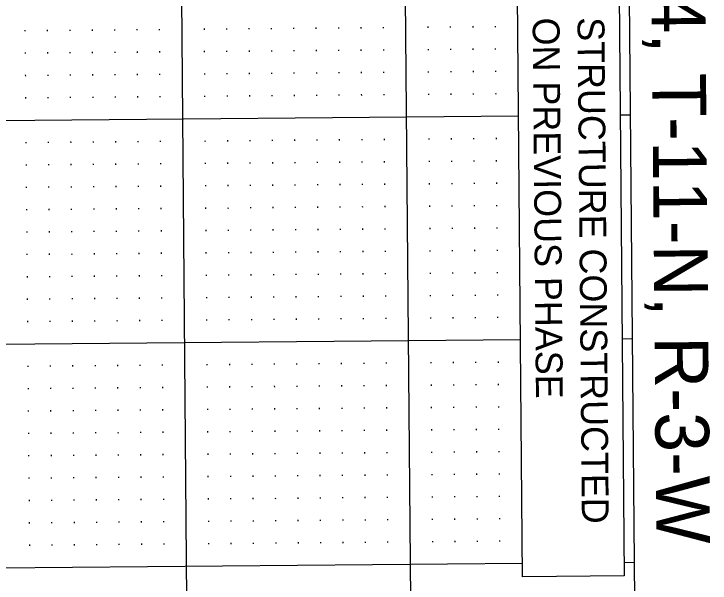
# Model space of a CAD drawing. Extents: x 2149873 to 2152007, y 140538 to 142349.
# Drawn here: x 2150345.4 to 2150500.9, y 141221.9 to 141349.1 of the extents above; entities that cross this region are included whole.
import ezdxf

# ---------------------------------------------------------------- set-up
doc = ezdxf.new("R2010")
doc.units = 0
for name, color, linetype in [('PLSS_Text', 7, 'Continuous'), ('PR_Grading_Txt', 7, 'Continuous'), ('PR_Misc_Improvement', 7, 'Continuous'), ('SHT_Profile_Grid_Major', 7, 'Continuous'), ('SHT_Profile_Grid_Minor', 7, 'Continuous'), ('SHT_Sheet_Border', 7, 'Continuous')]:
    doc.layers.add(name, color=color, linetype=linetype)

msp = doc.modelspace()

# ---------------------------------------------------------------- linework, layer by layer
at = {"layer": 'PR_Misc_Improvement'}
msp.add_lwpolyline([(2150480.33, 141379.55), (2150481.69, 141223.49), (2150459.02, 141223.29), (2150457.66, 141379.35)], close=True, dxfattribs=at)
at = {"layer": 'SHT_Profile_Grid_Major'}
for p, q in [((2150375.71, 142163.13), (2150389.5, 140588.19)), ((2150425.71, 142163.57), (2150439.49, 140588.63)), ((2149983.06, 141322.16), (2150458.12, 141326.32)), ((2149983.06, 141322.16), (2150458.12, 141326.32)), ((2150480.79, 141326.52), (2150483.04, 141326.54)), ((2150480.79, 141326.52), (2150483.04, 141326.54)), ((2149983.49, 141272.17), (2150458.56, 141276.32)), ((2150481.23, 141276.52), (2150483.48, 141276.54)), ((2149983.93, 141222.17), (2150458.99, 141226.33)), ((2150481.67, 141226.52), (2150483.91, 141226.54))]:
    msp.add_line(p, q, dxfattribs=at)
at = {"layer": 'SHT_Profile_Grid_Minor'}
for p, q in [((2150347.87, 141345.48), (2150347.87, 141345.23)), ((2150352.87, 141345.53), (2150352.87, 141345.28)), ((2150357.87, 141345.57), (2150357.87, 141345.32)), ((2150362.87, 141345.61), (2150362.87, 141345.36)), ((2150367.87, 141345.66), (2150367.87, 141345.41)), ((2150372.87, 141345.7), (2150372.87, 141345.45)), ((2150377.87, 141345.74), (2150377.87, 141345.49)), ((2150387.86, 141345.83), (2150387.87, 141345.58)), ((2150392.86, 141345.88), (2150392.87, 141345.63)), ((2150397.86, 141345.92), (2150397.87, 141345.67)), ((2150402.86, 141345.96), (2150402.87, 141345.71)), ((2150407.86, 141346.01), (2150407.87, 141345.76)), ((2150412.86, 141346.05), (2150412.87, 141345.8)), ((2150417.86, 141346.09), (2150417.87, 141345.85)), ((2150422.86, 141346.14), (2150422.87, 141345.89)), ((2150427.86, 141346.18), (2150427.87, 141345.93)), ((2150437.86, 141346.27), (2150437.87, 141346.02)), ((2150442.86, 141346.31), (2150442.86, 141346.06)), ((2150447.86, 141346.36), (2150447.86, 141346.11)), ((2150452.86, 141346.4), (2150452.86, 141346.15)), ((2150372.91, 141340.7), (2150372.91, 141340.45)), ((2150377.91, 141340.75), (2150377.91, 141340.5)), ((2150387.91, 141340.83), (2150387.91, 141340.58)), ((2150392.91, 141340.88), (2150392.91, 141340.63)), ((2150397.91, 141340.92), (2150397.91, 141340.67)), ((2150402.91, 141340.96), (2150402.91, 141340.71)), ((2150407.91, 141341.01), (2150407.91, 141340.76)), ((2150412.91, 141341.05), (2150412.91, 141340.8)), ((2150417.91, 141341.1), (2150417.91, 141340.85)), ((2150422.91, 141341.14), (2150422.91, 141340.89)), ((2150427.91, 141341.18), (2150427.91, 141340.93)), ((2150437.91, 141341.27), (2150437.91, 141341.02)), ((2150442.91, 141341.31), (2150442.91, 141341.06)), ((2150447.91, 141341.36), (2150447.91, 141341.11)), ((2150452.91, 141341.4), (2150452.91, 141341.15)), ((2150347.91, 141340.48), (2150347.91, 141340.23)), ((2150352.91, 141340.53), (2150352.91, 141340.28)), ((2150357.91, 141340.57), (2150357.91, 141340.32)), ((2150362.91, 141340.61), (2150362.91, 141340.36)), ((2150367.91, 141340.66), (2150367.91, 141340.41)), ((2150412.95, 141336.05), (2150412.95, 141335.8)), ((2150417.95, 141336.1), (2150417.95, 141335.85)), ((2150422.95, 141336.14), (2150422.95, 141335.89)), ((2150427.95, 141336.18), (2150427.95, 141335.93)), ((2150437.95, 141336.27), (2150437.95, 141336.02)), ((2150442.95, 141336.31), (2150442.95, 141336.06)), ((2150447.95, 141336.36), (2150447.95, 141336.11)), ((2150452.95, 141336.4), (2150452.95, 141336.15)), ((2150347.95, 141335.48), (2150347.96, 141335.23)), ((2150352.95, 141335.53), (2150352.96, 141335.28)), ((2150357.95, 141335.57), (2150357.96, 141335.32)), ((2150362.95, 141335.61), (2150362.96, 141335.36)), ((2150367.95, 141335.66), (2150367.96, 141335.41)), ((2150372.95, 141335.7), (2150372.96, 141335.45)), ((2150377.95, 141335.75), (2150377.95, 141335.5)), ((2150387.95, 141335.83), (2150387.95, 141335.58)), ((2150392.95, 141335.88), (2150392.95, 141335.63)), ((2150397.95, 141335.92), (2150397.95, 141335.67)), ((2150402.95, 141335.96), (2150402.95, 141335.71)), ((2150407.95, 141336.01), (2150407.95, 141335.76)), ((2150447.99, 141331.36), (2150448, 141331.11)), ((2150452.99, 141331.4), (2150453, 141331.15)), ((2150348, 141330.48), (2150348, 141330.23)), ((2150353, 141330.53), (2150353, 141330.28)), ((2150358, 141330.57), (2150358, 141330.32)), ((2150363, 141330.61), (2150363, 141330.36)), ((2150368, 141330.66), (2150368, 141330.41)), ((2150373, 141330.7), (2150373, 141330.45)), ((2150378, 141330.75), (2150378, 141330.5)), ((2150388, 141330.83), (2150388, 141330.58)), ((2150393, 141330.88), (2150393, 141330.63)), ((2150398, 141330.92), (2150398, 141330.67)), ((2150403, 141330.96), (2150403, 141330.71)), ((2150408, 141331.01), (2150408, 141330.76)), ((2150413, 141331.05), (2150413, 141330.8)), ((2150418, 141331.1), (2150418, 141330.85)), ((2150422.99, 141331.14), (2150423, 141330.89)), ((2150427.99, 141331.18), (2150428, 141330.93)), ((2150437.99, 141331.27), (2150438, 141331.02)), ((2150442.99, 141331.31), (2150443, 141331.06)), ((2150348.09, 141320.48), (2150348.09, 141320.23)), ((2150353.09, 141320.53), (2150353.09, 141320.28)), ((2150358.08, 141320.57), (2150358.09, 141320.32)), ((2150363.08, 141320.61), (2150363.09, 141320.36)), ((2150368.08, 141320.66), (2150368.09, 141320.41)), ((2150373.08, 141320.7), (2150373.09, 141320.45)), ((2150378.08, 141320.75), (2150378.09, 141320.5)), ((2150388.08, 141320.83), (2150388.09, 141320.58)), ((2150393.08, 141320.88), (2150393.09, 141320.63)), ((2150398.08, 141320.92), (2150398.09, 141320.67)), ((2150403.08, 141320.96), (2150403.09, 141320.71)), ((2150408.08, 141321.01), (2150408.09, 141320.76)), ((2150413.08, 141321.05), (2150413.08, 141320.8)), ((2150418.08, 141321.1), (2150418.08, 141320.85)), ((2150423.08, 141321.14), (2150423.08, 141320.89)), ((2150428.08, 141321.18), (2150428.08, 141320.93)), ((2150438.08, 141321.27), (2150438.08, 141321.02)), ((2150443.08, 141321.31), (2150443.08, 141321.06)), ((2150448.08, 141321.36), (2150448.08, 141321.11)), ((2150453.08, 141321.4), (2150453.08, 141321.15)), ((2150388.13, 141315.83), (2150388.13, 141315.58)), ((2150393.13, 141315.88), (2150393.13, 141315.63)), ((2150398.13, 141315.92), (2150398.13, 141315.67)), ((2150403.13, 141315.96), (2150403.13, 141315.71)), ((2150408.13, 141316.01), (2150408.13, 141315.76)), ((2150413.13, 141316.05), (2150413.13, 141315.8)), ((2150418.13, 141316.1), (2150418.13, 141315.85)), ((2150423.13, 141316.14), (2150423.13, 141315.89)), ((2150428.13, 141316.18), (2150428.13, 141315.93)), ((2150438.13, 141316.27), (2150438.13, 141316.02)), ((2150443.13, 141316.31), (2150443.13, 141316.06)), ((2150448.13, 141316.36), (2150448.13, 141316.11)), ((2150453.12, 141316.4), (2150453.13, 141316.15)), ((2150348.13, 141315.48), (2150348.13, 141315.23)), ((2150353.13, 141315.53), (2150353.13, 141315.28)), ((2150358.13, 141315.57), (2150358.13, 141315.32)), ((2150363.13, 141315.61), (2150363.13, 141315.36)), ((2150368.13, 141315.66), (2150368.13, 141315.41)), ((2150373.13, 141315.7), (2150373.13, 141315.45)), ((2150378.13, 141315.75), (2150378.13, 141315.5)), ((2150423.17, 141311.14), (2150423.17, 141310.89)), ((2150428.17, 141311.18), (2150428.17, 141310.93)), ((2150438.17, 141311.27), (2150438.17, 141311.02)), ((2150443.17, 141311.32), (2150443.17, 141311.07)), ((2150448.17, 141311.36), (2150448.17, 141311.11)), ((2150453.17, 141311.4), (2150453.17, 141311.15)), ((2150348.17, 141310.48), (2150348.17, 141310.23)), ((2150353.17, 141310.53), (2150353.17, 141310.28)), ((2150358.17, 141310.57), (2150358.17, 141310.32)), ((2150363.17, 141310.61), (2150363.17, 141310.36)), ((2150368.17, 141310.66), (2150368.17, 141310.41)), ((2150373.17, 141310.7), (2150373.17, 141310.45)), ((2150378.17, 141310.75), (2150378.17, 141310.5)), ((2150388.17, 141310.83), (2150388.17, 141310.58)), ((2150393.17, 141310.88), (2150393.17, 141310.63)), ((2150398.17, 141310.92), (2150398.17, 141310.67)), ((2150403.17, 141310.97), (2150403.17, 141310.72)), ((2150408.17, 141311.01), (2150408.17, 141310.76)), ((2150413.17, 141311.05), (2150413.17, 141310.8)), ((2150418.17, 141311.1), (2150418.17, 141310.85)), ((2150348.22, 141305.48), (2150348.22, 141305.23)), ((2150353.22, 141305.53), (2150353.22, 141305.28)), ((2150358.22, 141305.57), (2150358.22, 141305.32)), ((2150363.22, 141305.62), (2150363.22, 141305.37)), ((2150368.22, 141305.66), (2150368.22, 141305.41)), ((2150373.22, 141305.7), (2150373.22, 141305.45)), ((2150378.22, 141305.75), (2150378.22, 141305.5)), ((2150388.22, 141305.83), (2150388.22, 141305.58)), ((2150393.21, 141305.88), (2150393.22, 141305.63)), ((2150398.21, 141305.92), (2150398.22, 141305.67)), ((2150403.21, 141305.97), (2150403.22, 141305.72)), ((2150408.21, 141306.01), (2150408.22, 141305.76)), ((2150413.21, 141306.05), (2150413.22, 141305.8)), ((2150418.21, 141306.1), (2150418.22, 141305.85)), ((2150423.21, 141306.14), (2150423.22, 141305.89)), ((2150428.21, 141306.18), (2150428.22, 141305.93)), ((2150438.21, 141306.27), (2150438.22, 141306.02)), ((2150443.21, 141306.32), (2150443.22, 141306.07)), ((2150448.21, 141306.36), (2150448.21, 141306.11)), ((2150453.21, 141306.4), (2150453.21, 141306.15)), ((2150348.26, 141300.48), (2150348.26, 141300.23)), ((2150353.26, 141300.53), (2150353.26, 141300.28)), ((2150358.26, 141300.57), (2150358.26, 141300.32)), ((2150363.26, 141300.62), (2150363.26, 141300.37)), ((2150368.26, 141300.66), (2150368.26, 141300.41)), ((2150373.26, 141300.7), (2150373.26, 141300.45)), ((2150378.26, 141300.75), (2150378.26, 141300.5)), ((2150388.26, 141300.83), (2150388.26, 141300.58)), ((2150393.26, 141300.88), (2150393.26, 141300.63)), ((2150398.26, 141300.92), (2150398.26, 141300.67)), ((2150403.26, 141300.97), (2150403.26, 141300.72)), ((2150408.26, 141301.01), (2150408.26, 141300.76)), ((2150413.26, 141301.05), (2150413.26, 141300.8)), ((2150418.26, 141301.1), (2150418.26, 141300.85)), ((2150423.26, 141301.14), (2150423.26, 141300.89)), ((2150428.26, 141301.18), (2150428.26, 141300.93)), ((2150438.26, 141301.27), (2150438.26, 141301.02)), ((2150443.26, 141301.32), (2150443.26, 141301.07)), ((2150448.26, 141301.36), (2150448.26, 141301.11)), ((2150453.26, 141301.4), (2150453.26, 141301.15)), ((2150363.3, 141295.62), (2150363.31, 141295.37)), ((2150368.3, 141295.66), (2150368.31, 141295.41)), ((2150373.3, 141295.7), (2150373.31, 141295.45)), ((2150378.3, 141295.75), (2150378.31, 141295.5)), ((2150388.3, 141295.83), (2150388.3, 141295.58)), ((2150393.3, 141295.88), (2150393.3, 141295.63)), ((2150398.3, 141295.92), (2150398.3, 141295.67)), ((2150403.3, 141295.97), (2150403.3, 141295.72)), ((2150408.3, 141296.01), (2150408.3, 141295.76)), ((2150413.3, 141296.05), (2150413.3, 141295.8)), ((2150418.3, 141296.1), (2150418.3, 141295.85)), ((2150423.3, 141296.14), (2150423.3, 141295.89)), ((2150428.3, 141296.18), (2150428.3, 141295.93)), ((2150438.3, 141296.27), (2150438.3, 141296.02)), ((2150443.3, 141296.32), (2150443.3, 141296.07)), ((2150448.3, 141296.36), (2150448.3, 141296.11)), ((2150453.3, 141296.4), (2150453.3, 141296.15)), ((2150348.3, 141295.48), (2150348.31, 141295.23)), ((2150353.3, 141295.53), (2150353.31, 141295.28)), ((2150358.3, 141295.57), (2150358.31, 141295.32)), ((2150403.35, 141290.97), (2150403.35, 141290.72)), ((2150408.35, 141291.01), (2150408.35, 141290.76)), ((2150413.35, 141291.05), (2150413.35, 141290.8)), ((2150418.35, 141291.1), (2150418.35, 141290.85)), ((2150423.34, 141291.14), (2150423.35, 141290.89)), ((2150428.34, 141291.18), (2150428.35, 141290.93)), ((2150438.34, 141291.27), (2150438.35, 141291.02)), ((2150443.34, 141291.32), (2150443.35, 141291.07)), ((2150448.34, 141291.36), (2150448.35, 141291.11)), ((2150453.34, 141291.4), (2150453.35, 141291.15)), ((2150348.35, 141290.48), (2150348.35, 141290.23)), ((2150353.35, 141290.53), (2150353.35, 141290.28)), ((2150358.35, 141290.57), (2150358.35, 141290.32)), ((2150363.35, 141290.62), (2150363.35, 141290.37)), ((2150368.35, 141290.66), (2150368.35, 141290.41)), ((2150373.35, 141290.7), (2150373.35, 141290.45)), ((2150378.35, 141290.75), (2150378.35, 141290.5)), ((2150388.35, 141290.83), (2150388.35, 141290.58)), ((2150393.35, 141290.88), (2150393.35, 141290.63)), ((2150398.35, 141290.92), (2150398.35, 141290.67)), ((2150438.39, 141286.27), (2150438.39, 141286.02)), ((2150443.39, 141286.32), (2150443.39, 141286.07)), ((2150448.39, 141286.36), (2150448.39, 141286.11)), ((2150453.39, 141286.4), (2150453.39, 141286.15)), ((2150348.39, 141285.48), (2150348.39, 141285.23)), ((2150353.39, 141285.53), (2150353.39, 141285.28)), ((2150358.39, 141285.57), (2150358.39, 141285.32)), ((2150363.39, 141285.62), (2150363.39, 141285.37)), ((2150368.39, 141285.66), (2150368.39, 141285.41)), ((2150373.39, 141285.7), (2150373.39, 141285.45)), ((2150378.39, 141285.75), (2150378.39, 141285.5)), ((2150388.39, 141285.83), (2150388.39, 141285.58)), ((2150393.39, 141285.88), (2150393.39, 141285.63)), ((2150398.39, 141285.92), (2150398.39, 141285.67)), ((2150403.39, 141285.97), (2150403.39, 141285.72)), ((2150408.39, 141286.01), (2150408.39, 141285.76)), ((2150413.39, 141286.05), (2150413.39, 141285.8)), ((2150418.39, 141286.1), (2150418.39, 141285.85)), ((2150423.39, 141286.14), (2150423.39, 141285.89)), ((2150428.39, 141286.18), (2150428.39, 141285.93)), ((2150348.44, 141280.48), (2150348.44, 141280.23)), ((2150353.44, 141280.53), (2150353.44, 141280.28)), ((2150358.43, 141280.57), (2150358.44, 141280.32)), ((2150363.43, 141280.62), (2150363.44, 141280.37)), ((2150368.43, 141280.66), (2150368.44, 141280.41)), ((2150373.43, 141280.7), (2150373.44, 141280.45)), ((2150378.43, 141280.75), (2150378.44, 141280.5)), ((2150388.43, 141280.83), (2150388.44, 141280.58)), ((2150393.43, 141280.88), (2150393.44, 141280.63)), ((2150398.43, 141280.92), (2150398.44, 141280.67)), ((2150403.43, 141280.97), (2150403.44, 141280.72)), ((2150408.43, 141281.01), (2150408.44, 141280.76)), ((2150413.43, 141281.05), (2150413.44, 141280.8)), ((2150418.43, 141281.1), (2150418.43, 141280.85)), ((2150423.43, 141281.14), (2150423.43, 141280.89)), ((2150428.43, 141281.19), (2150428.43, 141280.94)), ((2150438.43, 141281.27), (2150438.43, 141281.02)), ((2150443.43, 141281.32), (2150443.43, 141281.07)), ((2150448.43, 141281.36), (2150448.43, 141281.11)), ((2150453.43, 141281.4), (2150453.43, 141281.15)), ((2150378.52, 141270.75), (2150378.52, 141270.5)), ((2150388.52, 141270.84), (2150388.52, 141270.59)), ((2150393.52, 141270.88), (2150393.52, 141270.63)), ((2150398.52, 141270.92), (2150398.52, 141270.67)), ((2150403.52, 141270.97), (2150403.52, 141270.72)), ((2150408.52, 141271.01), (2150408.52, 141270.76)), ((2150413.52, 141271.05), (2150413.52, 141270.8)), ((2150418.52, 141271.1), (2150418.52, 141270.85)), ((2150423.52, 141271.14), (2150423.52, 141270.89)), ((2150428.52, 141271.19), (2150428.52, 141270.94)), ((2150438.52, 141271.27), (2150438.52, 141271.02)), ((2150443.52, 141271.32), (2150443.52, 141271.07)), ((2150448.52, 141271.36), (2150448.52, 141271.11)), ((2150453.52, 141271.4), (2150453.52, 141271.15)), ((2150348.52, 141270.49), (2150348.53, 141270.24)), ((2150353.52, 141270.53), (2150353.52, 141270.28)), ((2150358.52, 141270.57), (2150358.52, 141270.32)), ((2150363.52, 141270.62), (2150363.52, 141270.37)), ((2150368.52, 141270.66), (2150368.52, 141270.41)), ((2150373.52, 141270.7), (2150373.52, 141270.45)), ((2150418.56, 141266.1), (2150418.57, 141265.85)), ((2150423.56, 141266.14), (2150423.57, 141265.89)), ((2150428.56, 141266.19), (2150428.57, 141265.94)), ((2150438.56, 141266.27), (2150438.57, 141266.02)), ((2150443.56, 141266.32), (2150443.57, 141266.07)), ((2150448.56, 141266.36), (2150448.57, 141266.11)), ((2150453.56, 141266.4), (2150453.56, 141266.15)), ((2150348.57, 141265.49), (2150348.57, 141265.24)), ((2150353.57, 141265.53), (2150353.57, 141265.28)), ((2150358.57, 141265.57), (2150358.57, 141265.32)), ((2150363.57, 141265.62), (2150363.57, 141265.37)), ((2150368.57, 141265.66), (2150368.57, 141265.41)), ((2150373.57, 141265.7), (2150373.57, 141265.45)), ((2150378.57, 141265.75), (2150378.57, 141265.5)), ((2150388.57, 141265.84), (2150388.57, 141265.59)), ((2150393.56, 141265.88), (2150393.57, 141265.63)), ((2150398.56, 141265.92), (2150398.57, 141265.67)), ((2150403.56, 141265.97), (2150403.57, 141265.72)), ((2150408.56, 141266.01), (2150408.57, 141265.76)), ((2150413.56, 141266.05), (2150413.57, 141265.8)), ((2150453.61, 141261.4), (2150453.61, 141261.15)), ((2150348.61, 141260.49), (2150348.61, 141260.24)), ((2150353.61, 141260.53), (2150353.61, 141260.28)), ((2150358.61, 141260.57), (2150358.61, 141260.32)), ((2150363.61, 141260.62), (2150363.61, 141260.37)), ((2150368.61, 141260.66), (2150368.61, 141260.41)), ((2150373.61, 141260.7), (2150373.61, 141260.45)), ((2150378.61, 141260.75), (2150378.61, 141260.5)), ((2150388.61, 141260.84), (2150388.61, 141260.59)), ((2150393.61, 141260.88), (2150393.61, 141260.63)), ((2150398.61, 141260.92), (2150398.61, 141260.67)), ((2150403.61, 141260.97), (2150403.61, 141260.72)), ((2150408.61, 141261.01), (2150408.61, 141260.76)), ((2150413.61, 141261.05), (2150413.61, 141260.8)), ((2150418.61, 141261.1), (2150418.61, 141260.85)), ((2150423.61, 141261.14), (2150423.61, 141260.89)), ((2150428.61, 141261.19), (2150428.61, 141260.94)), ((2150438.61, 141261.27), (2150438.61, 141261.02)), ((2150443.61, 141261.32), (2150443.61, 141261.07)), ((2150448.61, 141261.36), (2150448.61, 141261.11)), ((2150348.65, 141255.49), (2150348.66, 141255.24)), ((2150353.65, 141255.53), (2150353.66, 141255.28)), ((2150358.65, 141255.57), (2150358.66, 141255.32)), ((2150363.65, 141255.62), (2150363.66, 141255.37)), ((2150368.65, 141255.66), (2150368.66, 141255.41)), ((2150373.65, 141255.7), (2150373.66, 141255.45)), ((2150378.65, 141255.75), (2150378.66, 141255.5)), ((2150388.65, 141255.84), (2150388.65, 141255.59)), ((2150393.65, 141255.88), (2150393.65, 141255.63)), ((2150398.65, 141255.92), (2150398.65, 141255.67)), ((2150403.65, 141255.97), (2150403.65, 141255.72)), ((2150408.65, 141256.01), (2150408.65, 141255.76)), ((2150413.65, 141256.05), (2150413.65, 141255.8)), ((2150418.65, 141256.1), (2150418.65, 141255.85)), ((2150423.65, 141256.14), (2150423.65, 141255.89)), ((2150428.65, 141256.19), (2150428.65, 141255.94)), ((2150438.65, 141256.27), (2150438.65, 141256.02)), ((2150443.65, 141256.32), (2150443.65, 141256.07)), ((2150448.65, 141256.36), (2150448.65, 141256.11)), ((2150453.65, 141256.4), (2150453.65, 141256.15)), ((2150353.7, 141250.53), (2150353.7, 141250.28)), ((2150358.7, 141250.57), (2150358.7, 141250.32)), ((2150363.7, 141250.62), (2150363.7, 141250.37)), ((2150368.7, 141250.66), (2150368.7, 141250.41)), ((2150373.7, 141250.7), (2150373.7, 141250.45)), ((2150378.7, 141250.75), (2150378.7, 141250.5)), ((2150388.7, 141250.84), (2150388.7, 141250.59)), ((2150393.7, 141250.88), (2150393.7, 141250.63)), ((2150398.7, 141250.92), (2150398.7, 141250.67)), ((2150403.7, 141250.97), (2150403.7, 141250.72)), ((2150408.7, 141251.01), (2150408.7, 141250.76)), ((2150413.7, 141251.05), (2150413.7, 141250.8)), ((2150418.7, 141251.1), (2150418.7, 141250.85)), ((2150423.7, 141251.14), (2150423.7, 141250.89)), ((2150428.69, 141251.19), (2150428.7, 141250.94)), ((2150438.69, 141251.27), (2150438.7, 141251.02)), ((2150443.69, 141251.32), (2150443.7, 141251.07)), ((2150448.69, 141251.36), (2150448.7, 141251.11)), ((2150453.69, 141251.4), (2150453.7, 141251.15)), ((2150348.7, 141250.49), (2150348.7, 141250.24)), ((2150393.74, 141245.88), (2150393.74, 141245.63)), ((2150398.74, 141245.92), (2150398.74, 141245.67)), ((2150403.74, 141245.97), (2150403.74, 141245.72)), ((2150408.74, 141246.01), (2150408.74, 141245.76)), ((2150413.74, 141246.06), (2150413.74, 141245.81)), ((2150418.74, 141246.1), (2150418.74, 141245.85)), ((2150423.74, 141246.14), (2150423.74, 141245.89)), ((2150428.74, 141246.19), (2150428.74, 141245.94)), ((2150438.74, 141246.27), (2150438.74, 141246.02)), ((2150443.74, 141246.32), (2150443.74, 141246.07)), ((2150448.74, 141246.36), (2150448.74, 141246.11)), ((2150453.74, 141246.41), (2150453.74, 141246.16)), ((2150348.74, 141245.49), (2150348.74, 141245.24)), ((2150353.74, 141245.53), (2150353.74, 141245.28)), ((2150358.74, 141245.57), (2150358.74, 141245.32)), ((2150363.74, 141245.62), (2150363.74, 141245.37)), ((2150368.74, 141245.66), (2150368.74, 141245.41)), ((2150373.74, 141245.7), (2150373.74, 141245.45)), ((2150378.74, 141245.75), (2150378.74, 141245.5)), ((2150388.74, 141245.84), (2150388.74, 141245.59)), ((2150428.78, 141241.19), (2150428.78, 141240.94)), ((2150438.78, 141241.27), (2150438.78, 141241.02)), ((2150443.78, 141241.32), (2150443.78, 141241.07)), ((2150448.78, 141241.36), (2150448.78, 141241.11)), ((2150453.78, 141241.41), (2150453.78, 141241.16)), ((2150348.79, 141240.49), (2150348.79, 141240.24)), ((2150353.79, 141240.53), (2150353.79, 141240.28)), ((2150358.79, 141240.57), (2150358.79, 141240.32)), ((2150363.78, 141240.62), (2150363.79, 141240.37)), ((2150368.78, 141240.66), (2150368.79, 141240.41)), ((2150373.78, 141240.71), (2150373.79, 141240.46)), ((2150378.78, 141240.75), (2150378.79, 141240.5)), ((2150388.78, 141240.84), (2150388.79, 141240.59)), ((2150393.78, 141240.88), (2150393.79, 141240.63)), ((2150398.78, 141240.92), (2150398.79, 141240.67)), ((2150403.78, 141240.97), (2150403.79, 141240.72)), ((2150408.78, 141241.01), (2150408.79, 141240.76)), ((2150413.78, 141241.06), (2150413.79, 141240.81)), ((2150418.78, 141241.1), (2150418.78, 141240.85)), ((2150423.78, 141241.14), (2150423.78, 141240.89)), ((2150348.83, 141235.49), (2150348.83, 141235.24)), ((2150353.83, 141235.53), (2150353.83, 141235.28)), ((2150358.83, 141235.57), (2150358.83, 141235.32)), ((2150363.83, 141235.62), (2150363.83, 141235.37)), ((2150368.83, 141235.66), (2150368.83, 141235.41)), ((2150373.83, 141235.71), (2150373.83, 141235.46)), ((2150378.83, 141235.75), (2150378.83, 141235.5)), ((2150388.83, 141235.84), (2150388.83, 141235.59)), ((2150393.83, 141235.88), (2150393.83, 141235.63)), ((2150398.83, 141235.92), (2150398.83, 141235.67)), ((2150403.83, 141235.97), (2150403.83, 141235.72)), ((2150408.83, 141236.01), (2150408.83, 141235.76)), ((2150413.83, 141236.06), (2150413.83, 141235.81)), ((2150418.83, 141236.1), (2150418.83, 141235.85)), ((2150423.83, 141236.14), (2150423.83, 141235.89)), ((2150428.83, 141236.19), (2150428.83, 141235.94)), ((2150438.83, 141236.27), (2150438.83, 141236.02)), ((2150443.83, 141236.32), (2150443.83, 141236.07)), ((2150448.83, 141236.36), (2150448.83, 141236.11)), ((2150453.83, 141236.41), (2150453.83, 141236.16)), ((2150348.87, 141230.49), (2150348.88, 141230.24)), ((2150353.87, 141230.53), (2150353.88, 141230.28)), ((2150358.87, 141230.57), (2150358.87, 141230.32)), ((2150363.87, 141230.62), (2150363.87, 141230.37)), ((2150368.87, 141230.66), (2150368.87, 141230.41)), ((2150373.87, 141230.71), (2150373.87, 141230.46)), ((2150378.87, 141230.75), (2150378.87, 141230.5)), ((2150388.87, 141230.84), (2150388.87, 141230.59)), ((2150393.87, 141230.88), (2150393.87, 141230.63)), ((2150398.87, 141230.92), (2150398.87, 141230.67)), ((2150403.87, 141230.97), (2150403.87, 141230.72)), ((2150408.87, 141231.01), (2150408.87, 141230.76)), ((2150413.87, 141231.06), (2150413.87, 141230.81)), ((2150418.87, 141231.1), (2150418.87, 141230.85)), ((2150423.87, 141231.14), (2150423.87, 141230.89)), ((2150428.87, 141231.19), (2150428.87, 141230.94)), ((2150438.87, 141231.27), (2150438.87, 141231.02)), ((2150443.87, 141231.32), (2150443.87, 141231.07)), ((2150448.87, 141231.36), (2150448.87, 141231.11)), ((2150453.87, 141231.41), (2150453.87, 141231.16))]:
    msp.add_line(p, q, dxfattribs=at)
at = {"layer": 'SHT_Sheet_Border'}
msp.add_line((2150475.71, 142164.01), (2150489.49, 140589.07), dxfattribs=at)

# ---------------------------------------------------------------- texts
at = {"layer": 'PLSS_Text'}
msp.add_text('SEC. 34, T-11-N, R-3-W', height=12, rotation=270.5015, dxfattribs=at).set_placement((2150487.36, 141404.51))
at = {"layer": 'PR_Grading_Txt'}
for s, p in [('ON PREVIOUS PHASE', (2150461.25, 141348.26)), ('STRUCTURE CONSTRUCTED', (2150471.27, 141348.35))]:
    msp.add_text(s, height=6, rotation=270.5015, dxfattribs=at).set_placement(p)

doc.saveas('drawing.dxf')
